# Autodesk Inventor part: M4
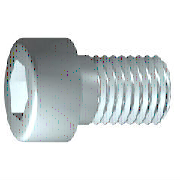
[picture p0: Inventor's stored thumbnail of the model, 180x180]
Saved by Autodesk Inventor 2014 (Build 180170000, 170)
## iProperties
IsCustomPart: 0
Created: 2016-04
Part Number: M4
Material: 강철, 연강
Description: 6각머리 태핑 나사
Document SubType Name: Modeling
Standard: KS B 1003
Designer: mdu
Standards Organization: KS
Language: ko-KR
Size Designation: M 4 x 10
Categories: <MemberInstance><Categories><Category DisplayName="조임쇠" InternalName="e4da775c-781d-43d5-af7c-5136215cf5a6" Mnemonic="FSTN"><Category DisplayName="볼트" InternalN
Density: 7.86 g/cm^3
Mass: 2.0371 g
Surface Area: 3.0572 cm^2
Volume: 0.259174 cm^3
Appearance: 강철
Author: mdu
Revision Number: 1
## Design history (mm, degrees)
sketch "스케치1"
  geometry: L1 (-1, 0)-(10, 0); L2 (10, 0)-(10, 2); L3 (10, 2)-(1.75, 2); L4 (1.75, 2)-(1.32, 2); L5 (1.32, 2)-(0, 2); L6 (0, 2)-(0, 3.5); L7 (0, 3.5)-(-4, 3.5); L8 (-4, 3.5)-(-4, 1.732); L9 (-4, 1.732)-(-2, 1.732); L10 (-2, 1.732)-(-1, 0); L11 (-6.8, 0)-(12.8, 0) reference; L12 (0, -0.7)-(0, 4.2) reference; L13 (1.75, 2)-(0, 2)
  constraints: 22 end point, 6 parallel, 2 collinear, 2 perpendicular, 1 horizontal, 1 point on line
  dimensions: "d1" = 8.25 distance from line of L3.end L2 (= GEL); "d2" = 0.42952 distance of L4.end L3.end (computed from GAL); "d3" = 4 distance between parallel lines of L8 L6 (= KOH); "d4" = 2 distance of L8.end L9.end (= INTI); "d5" = 60 deg angle of L10 L1; "d6" = 4 diameter of L3 L1 (= GD); "d7" = 4 diameter of L5 L1 (= BDM); "d8" = 3.4641 diameter of L9 L1 (= 1.1547 x SW); "d9" = 7 diameter of L7 L1 (= KOD); "d26" = 10 distance between parallel lines of L12 L2 (= NLG)
revolve "본체" sketch "스케치1" stored, may be unused: angle "d10" = 90 deg
sketch "스케치2"
  geometry: L1 (0, -4.9)-(0, 4.9) reference; L2 (-4.9, 0)-(4.9, 0) reference; L3 (1.732, 0)-(0.866, -1.5); L4 (0.866, -1.5)-(-0.866, -1.5); L5 (-0.866, -1.5)-(-1.732, 0); L6 (-1.732, 0)-(-0.866, 1.5); L7 (-0.866, 1.5)-(0.866, 1.5); L8 (0.866, 1.5)-(1.732, 0); 2 further points
  constraints: 12 end point, 1 coincident, 1 horizontal alignment, 1 point on line, 12 other
extrude "슬롯" join sketch "스케치2" stored distance "d11" = 10; taper "d12" = 0 deg
workplane "Work Plane1"
fillet "Fillet2" dims "d30" = 0.1 (= R)
body "Solid1"
fillet "모깎기1" dims "d17" = 0.4 (= RR)
feature "스레드" dims "d13" = 8.25 (= GEL), "d14" = 0
chamfer "모따기1" distance "d15" = 0.42941 (= -0.5 x SPD + 0.5 x GD); stored, may be unused: second distance "d16" = 0.42941 (= GUL), angle "d27" = 45 deg
other parameters: "GD" = 4 (= NND) [user parameter; used in 2 equation terms], "NLG" = 10 [user parameter; used in 1 equation term], "GEL" = 8.25 [user parameter; used in 2 equation terms], "KOD" = 7 [user parameter; used in 1 equation term], "KOH" = 4 [user parameter; used in 1 equation term], "INTI" = 2 [user parameter; used in 1 equation term], "GAL" = 0.42941 (= 0.61345 x PTC) [user parameter; used in 1 equation term], "GUL" = 0.42941 (= 0.61345 x PTC) [user parameter; used in 1 equation term], "BDM" = 4 (= NND) [user parameter; used in 1 equation term], "SW" = 3 [user parameter; used in 2 equation terms], "RR" = 0.4 [user parameter; used in 1 equation term], "SPD" = 3.14117 (= NND - 1.2269 x PTC) [user parameter; used in 1 equation term], "d19" = 0, "d28" = 0, "d29" = 0, "R" = 0.1 [user parameter; used in 1 equation term], "PHH" = 0.2 [user parameter], "GD1" = 3.14117 (= THREADDIA - 1.2269 x PTC) [user parameter], "THREADDIA" = 4 [user parameter; used in 1 equation term], "FAWI" = 45 deg [user parameter], "TPU" = 14.28571 (computed from PTC) [user parameter], "PTC" = 0.7 [user parameter; used in 5 equation terms], "NND" = 4 [user parameter; used in 3 equation terms], "TOA" = 30 deg [user parameter], "E0" = 3.465 (= 1.155 x SW) [user parameter]
